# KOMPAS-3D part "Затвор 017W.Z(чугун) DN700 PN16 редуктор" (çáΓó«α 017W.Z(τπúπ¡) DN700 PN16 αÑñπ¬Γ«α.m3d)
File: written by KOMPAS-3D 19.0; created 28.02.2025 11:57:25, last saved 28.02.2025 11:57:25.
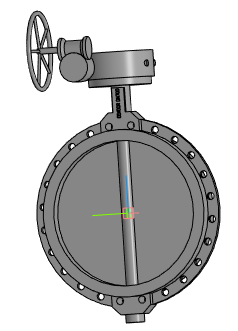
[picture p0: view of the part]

Document properties: Автор: Евгений; Полное имя файла: Затвор 017W.Z(чугун) DN700 PN16 редуктор.a3d

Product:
- Part/product: Затвор 017W.Z(чугун) DN700 PN16 редуктор
    Масса: 444.712

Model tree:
1. Операция без истории:1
